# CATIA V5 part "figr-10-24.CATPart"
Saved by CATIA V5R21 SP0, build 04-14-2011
Part number: Part1
Bounding box of the stored display mesh (mm): x -92.502 to 25.581, y -200.404 to 0, z 0 to 47.305
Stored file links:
  D:\CATIA V5R21 E-RESOURCES\CATIA-V5R21\catia-v5r21-prt\c10-catia-v5r20-prt\c10-catia-v5r21-figr-10-24.CATPart
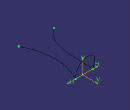
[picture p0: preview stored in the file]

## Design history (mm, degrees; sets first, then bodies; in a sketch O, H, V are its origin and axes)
Set1
  Sketch1 on xy-plane, origin (0, 0, 0), H (1, 0, 0), V (0, 1, 0)
    spline S1 through (-36.6295, 0) (-39.5961, -76.7629) (-56.6868, -154.7631) (-92.5015, -194.2587)
    point P1 (-36.6295, 0)
    coincidence: P1 H
  Sketch2 on xy-plane, origin (0, 0, 0), H (1, 0, 0), V (0, 1, 0)
    spline S1 through (25.5807, 0) (5.5021, -50.6307) (25.5807, -200.404)
    point P1 (25.5807, 0)
    coincidence: P1 H
  Sketch3 on zx-plane, origin (0, 0, 0), H (-1, 0, 0), V (0, 0, 1)
    spline S1 through (-25.5807, 0) (16.4189, 47.2175) (28.9802, 46.33) (36.6295, 0)
    reference projected point E1 (36.6295, 0) from vertex of Sketch1
    reference projected point E2 (-25.5807, 0) from vertex of Sketch2
    point P1 (-25.5807, 0)
    point P2 (36.6295, 0)
    coincidence: P1 H, P2 H, E1 P2, P1 E2
Body1 (main body)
